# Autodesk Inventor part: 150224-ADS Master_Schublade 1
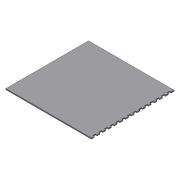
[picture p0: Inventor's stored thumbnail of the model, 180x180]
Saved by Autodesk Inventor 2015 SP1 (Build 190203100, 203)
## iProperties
Created: 2015-02
Part Number: 150224-ADS Master_Schublade 1
Material: Generic
Document SubType Name: Modeling
Designer: SATurn
Density: 1 g/cm^3
Appearance: Default
Description: 150224-ADS Master_Schublade
ILogicFactory: False
Author: SATurn
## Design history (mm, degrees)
sketch "Master_Schublade"
  geometry: L1 (242, 290)-(-242, 290); L2 (-242, 290)-(-242, -290); L3 (-242, -290)-(242, -290); L4 (242, -290)-(242, 290); L5 (242, 290)-(-242, -290); L6 (-242, 290)-(242, -290); 1 further point
  constraints: 12 end point, 2 midpoint, 2 parallel, 1 horizontal, 1 perpendicular
  dimensions: "d0" = 484 distance of L3.end L2.end (= L); "d1" = 580 distance of L2.end L1.end (= B)
extrude "Extrusion1" new body sketch "Master_Schublade" distance "d4" = 8 (= H_Boden); taper "d5" = 0 deg
sketch "Sketch3"
  geometry: L1 (-242, 290)-(-242, -290) reference; L2 (242, 290)-(-242, 290) reference; L3 (242, -290)-(242, 290) reference; L4 (-242, -290)-(242, -290) reference; L5 (-242, 290)-(-222, 290); L6 (-222, 290)-(-222, 280); L7 (-222, 280)-(-242, 280); L8 (-242, 280)-(-242, 290); L9 (-242, 260)-(-232, 260); L10 (-232, 260)-(-232, 240); L11 (-232, 240)-(-242, 240); L12 (-242, 240)-(-242, 260); L13 (0, 290)-(0, -290); L14 (-222, 280)-(-222, 290); L15 (-222, 290)-(-202, 290); L16 (-202, 290)-(-202, 280); L17 (-202, 280)-(-222, 280); 1 further point
  constraints: 26 end point, 6 parallel, 4 perpendicular, 2 collinear, 2 horizontal, 2 midpoint
  dimensions: "d8" = 580 distance of L3.start L2.start (derived); "d9" = 484 distance of L2.start L1.start (derived); "d11" = 10 distance of L5.end L6.end (= T_Zinken); "d12" = 20 distance of L1.start L5.end (= B_Zinken); "d13" = 20 distance of L11.end L9.start (= B_Zinken); "d14" = 10 distance of L10.end L11.end (= T_Zinken); "d15" = 20 distance between parallel lines of L9 L7 (= B_Zinken)
extrude "Extrusion2" cut sketch "Sketch3" stored distance "d21" = 0; taper "d22" = 0 deg
extrude_surface "ExtrusionSrf1" dims "d16" = 10, "d17" = 0
pattern_linear "Rectangular Pattern1" dims "d20" = 40 (= 2 x B_Zinken)
sketch "Sketch5"
  geometry: L1 (580, -2)-(560, -2) reference; L2 (560, -2)-(560, 8) reference; L3 (560, 8)-(580, 8) reference; L4 (580, 8)-(580, -2) reference; L5 (540, -2)-(520, -2) reference; L6 (520, -2)-(520, 8) reference; L7 (520, 8)-(540, 8) reference; L8 (540, 8)-(540, -2) reference; L9 (500, -2)-(480, -2) reference; L10 (480, -2)-(480, 8) reference; L11 (480, 8)-(500, 8) reference; L12 (500, 8)-(500, -2) reference; L13 (460, -2)-(440, -2) reference; L14 (440, -2)-(440, 8) reference; L15 (440, 8)-(460, 8) reference; L16 (460, 8)-(460, -2) reference; L17 (420, -2)-(400, -2) reference; L18 (400, -2)-(400, 8) reference; L19 (400, 8)-(420, 8) reference; L20 (420, 8)-(420, -2) reference; L21 (380, -2)-(360, -2) reference; L22 (360, -2)-(360, 8) reference; L23 (360, 8)-(380, 8) reference; L24 (380, 8)-(380, -2) reference; L25 (340, -2)-(320, -2) reference; L26 (320, -2)-(320, 8) reference; L27 (320, 8)-(340, 8) reference; L28 (340, 8)-(340, -2) reference; L29 (300, -2)-(280, -2) reference; L30 (280, -2)-(280, 8) reference; L31 (280, 8)-(300, 8) reference; L32 (300, 8)-(300, -2) reference; L33 (260, -2)-(240, -2) reference; L34 (240, -2)-(240, 8) reference; L35 (240, 8)-(260, 8) reference; L36 (260, 8)-(260, -2) reference; L37 (220, -2)-(200, -2) reference; L38 (200, -2)-(200, 8) reference; L39 (200, 8)-(220, 8) reference; L40 (220, 8)-(220, -2) reference; L41 (180, -2)-(160, -2) reference; L42 (160, -2)-(160, 8) reference; L43 (160, 8)-(180, 8) reference; L44 (180, 8)-(180, -2) reference; L45 (140, -2)-(120, -2) reference; L46 (120, -2)-(120, 8) reference; L47 (120, 8)-(140, 8) reference; L48 (140, 8)-(140, -2) reference; L49 (100, -2)-(80, -2) reference; L50 (80, -2)-(80, 8) reference; L51 (80, 8)-(100, 8) reference; L52 (100, 8)-(100, -2) reference; L53 (60, -2)-(40, -2) reference; L54 (40, -2)-(40, 8) reference; L55 (40, 8)-(60, 8) reference; L56 (60, 8)-(60, -2) reference; L57 (20, -2)-(0, -2) reference; L58 (0, -2)-(0, 8) reference; L59 (0, 8)-(20, 8) reference; L60 (20, 8)-(20, -2) reference; 1 further point
  node "Project Cut Edges3"
body "Solid1"
body "Srf1"
other parameters: "B" = 580 [user parameter; used in 1 equation term], "L" = 484 [user parameter; used in 2 equation terms], "B_Zinken" = 20 [user parameter; used in 5 equation terms], "H_Boden" = 8 [user parameter; used in 1 equation term], "T_Zinken" = 10 [user parameter; used in 2 equation terms]
